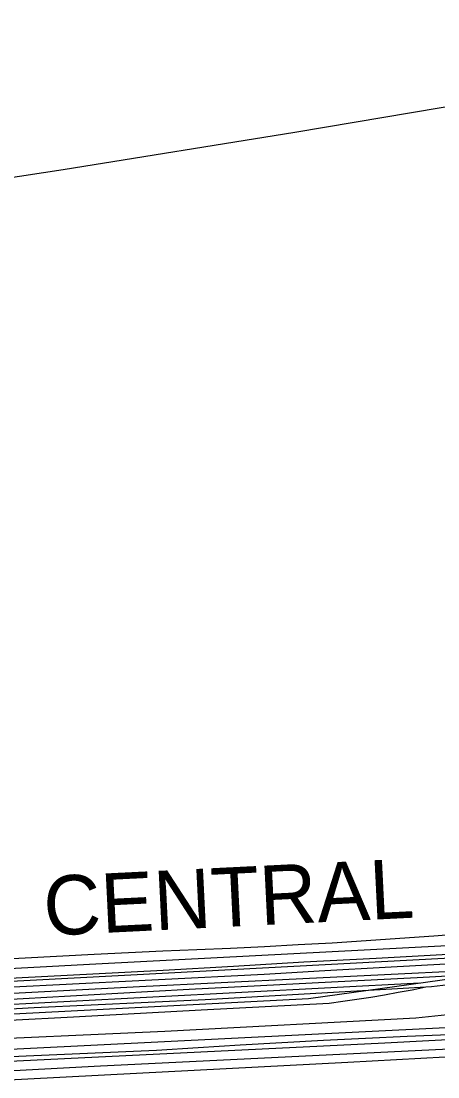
# Model space of a CAD drawing. Extents: x 3508733 to 3546731, y 546897 to 572481.
# Drawn here: x 3516762 to 3517344, y 567889 to 569367 of the extents above; entities that cross this region are included whole.
import ezdxf

# ---------------------------------------------------------------- set-up
doc = ezdxf.new("R2010")
doc.units = 0
for name, color, linetype in [('V-DTCH-CNTR', 7, 'Continuous'), ('V-RAIL-IDEN', 7, 'Continuous'), ('V-RAIL-TRAK', 7, 'Continuous'), ('V-ROAD-CNTR', 7, 'Continuous'), ('V-TOPO-SHOR', 7, 'Continuous')]:
    doc.layers.add(name, color=color, linetype=linetype)

msp = doc.modelspace()

# ---------------------------------------------------------------- linework, layer by layer
at = {"layer": 'V-DTCH-CNTR'}
for points in [[(3518426.588, 569365.362), (3518194.0670000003, 569343.415), (3517851.477, 569304.839), (3517537.957, 569270.982), (3517390.579, 569252.3200000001), (3517144.465, 569210.947), (3516820.739, 569158.495), (3516438.882, 569100.279), (3516292.9, 569076.452), (3516001.605, 569018.555)], [(3516671.532, 568051.006), (3516767.6720000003, 568056.139), (3516863.821, 568061.068), (3516959.981, 568065.799), (3517007.349, 568067.632), (3517054.7090000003, 568069.697), (3517102.057, 568071.99), (3517149.394, 568074.515), (3517196.717, 568077.27), (3517244.028, 568080.254), (3517291.323, 568083.4670000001), (3517338.603, 568086.912), (3517385.862, 568090.586), (3517433.106, 568094.49), (3517555.615, 568102.198), (3517785.2800000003, 568111.175), (3518030.47, 568123.776), (3518316.304, 568142.4720000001)]]:
    msp.add_lwpolyline(points, dxfattribs=at)
at = {"layer": 'V-RAIL-TRAK'}
for points in [[(3518351.019, 568114.087), (3517994.9420000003, 568095.057), (3517908.188, 568090.0970000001), (3517821.421, 568085.388), (3517734.6410000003, 568080.932), (3517647.847, 568076.725), (3517561.042, 568072.7710000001), (3517460.045, 568066.733), (3517359.038, 568060.904), (3517258.0160000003, 568055.285), (3517156.986, 568049.872), (3517058.6580000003, 568044.06), (3516960.315, 568038.479), (3516861.9590000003, 568033.129), (3516763.594, 568028.012), (3516631.881, 568020.637)], [(3516658.474, 568011.0380000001), (3516806.215, 568018.505), (3516953.958, 568025.925), (3517101.702, 568033.297), (3517186.295, 568038.323), (3517270.9, 568043.1630000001), (3517355.5130000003, 568047.81), (3517440.1380000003, 568052.268), (3517561.822, 568058.0480000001), (3517683.4960000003, 568064.062), (3517805.16, 568070.317), (3517926.809, 568076.809), (3518047.336, 568083.355), (3518167.8710000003, 568089.806), (3518288.41, 568096.165), (3518408.951, 568102.43), (3518489.861, 568106.165), (3518506.895, 568107.005), (3518570.757, 568110.153), (3518651.6410000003, 568114.39)], [(3518944.605, 568113.3740000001), (3518863.767, 568109.284), (3518703.052, 568101.457), (3518542.3310000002, 568093.812), (3518391.555, 568086.017), (3518240.79, 568077.983), (3518124.424, 568071.595), (3518090.039, 568069.709), (3517983.031, 568063.409), (3517876.006, 568057.366), (3517768.969, 568051.578), (3517661.921, 568046.044), (3517554.855, 568040.7660000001), (3517463.369, 568035.943), (3517435.191, 568034.459), (3517315.52, 568028.206), (3517195.849, 568022.013), (3517096.316, 568016.84), (3516996.79, 568011.562), (3516897.269, 568006.182), (3516797.755, 568000.693), (3516698.244, 567995.1)], [(3514632.095, 567871.17), (3515067.864, 567895.049), (3515329.14, 567908.8470000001), (3515365.572, 567910.772), (3515437.473, 567914.7220000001), (3515592.12, 567923.2220000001), (3515724.822, 567929.648), (3515852.7770000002, 567935.845), (3516133.963, 567951.345), (3516467.6520000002, 567968.837), (3516780.021, 567986.652), (3517019.09, 567997.736), (3517288.015, 568013.268), (3517327.523, 568015.382), (3517335.457, 568015.805), (3517351.544, 568017.653), (3517367.609, 568019.691), (3517383.646, 568021.921), (3517399.656, 568024.344), (3517415.636, 568026.959), (3517431.5840000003, 568029.763), (3517447.495, 568032.759), (3517463.369, 568035.943)], [(3515688.775, 567912.302), (3515729.616, 567914.927), (3515753.156, 567916.443), (3515817.549, 567920.387), (3515881.957, 567924.133), (3515946.372, 567927.68), (3516010.8000000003, 567931.031), (3516075.239, 567934.18), (3516220.573, 567941.502), (3516365.899, 567948.9670000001), (3516511.217, 567956.5750000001), (3516656.5270000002, 567964.331), (3516835.161, 567973.627), (3517013.788, 567983.113), (3517192.4020000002, 567992.792), (3517211.809, 567995.352), (3517231.187, 567998.133), (3517250.5330000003, 568001.14), (3517269.839, 568004.367), (3517289.111, 568007.818), (3517308.339, 568011.488), (3517327.523, 568015.382)], [(3517955.024, 567963.93), (3517946.724, 567961.046), (3517938.358, 567958.357), (3517929.93, 567955.863), (3517921.4450000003, 567953.5650000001), (3517912.907, 567951.461), (3517904.324, 567949.559), (3517895.698, 567947.855), (3517887.035, 567946.35), (3517878.339, 567945.047), (3517869.614, 567943.947), (3517860.867, 567943.0480000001), (3517852.102, 567942.354), (3517774.886, 567937.84), (3517697.656, 567933.564), (3517620.414, 567929.523), (3517543.159, 567925.718), (3517465.894, 567922.148), (3517388.619, 567918.814), (3517218.582, 567909.791), (3517048.54, 567900.823), (3516878.495, 567891.916), (3516708.447, 567883.066)], [(3517359.9760000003, 567948.537), (3517301.536, 567946.018), (3517243.105, 567943.276), (3517184.685, 567940.308), (3517126.276, 567937.1190000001), (3517067.882, 567933.705), (3517009.4990000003, 567930.068), (3516951.133, 567926.205), (3516876.1380000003, 567923.176), (3516801.15, 567919.928), (3516726.173, 567916.461)]]:
    msp.add_lwpolyline(points, dxfattribs=at)
at = {"layer": 'V-ROAD-CNTR'}
for points in [[(3521093.579774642, 568241.175491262), (3520798.753364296, 568217.342538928), (3520420.0671216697, 568201.5255705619), (3520267.1584274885, 568189.4725946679), (3519841.37827905, 568172.7476281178), (3519690.082581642, 568163.657646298), (3519221.228519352, 568133.27170707), (3518627.7027064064, 568097.0117795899), (3518514.3509331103, 568086.1288013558), (3518236.049489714, 568067.9378377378), (3518067.9988258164, 568075.11182339), (3517535.933889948, 568046.7418801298), (3517450.66806048, 568038.8758958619), (3517163.540634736, 567998.805976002), (3515683.694594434, 567921.754130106), (3515524.090913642, 567914.3611448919), (3515291.0693796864, 567900.9091717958), (3514216.1605295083, 567847.25227911), (3513979.474002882, 567857.10225941)], [(3518191.93657794, 568122.255729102), (3517571.750818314, 568083.99180563), (3516866.270229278, 568047.0918794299), (3516165.4296309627, 568009.3579548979), (3515708.402545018, 567981.5080105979), (3515316.140329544, 567964.803044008), (3514386.3821890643, 567914.4681446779), (3513892.8151762, 567898.4101767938), (3513315.912330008, 567858.51225659), (3512893.95217393, 567835.829301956)], [(3518542.79587622, 568118.0607374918), (3518357.489246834, 568109.178755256), (3517909.0841436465, 568085.4698026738), (3517484.710992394, 568062.228849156), (3516968.1700254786, 568034.56190449), (3515719.4745228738, 567968.4760366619), (3514984.8079922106, 567932.899107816), (3513660.4756408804, 567861.905249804), (3512913.6481345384, 567818.681336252)], [(3517498.096965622, 568043.2508871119), (3516927.445106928, 568015.382942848), (3515733.3034952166, 567952.6120683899), (3515145.000671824, 567920.3921328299), (3513966.9600279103, 567863.441246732), (3513481.253999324, 567836.200301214), (3512928.204105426, 567802.83736794)], [(3517319.3583231, 568020.5509325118), (3516697.0175677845, 567988.162997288), (3515719.543522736, 567941.51709058), (3515389.0901836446, 567922.1601292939)], [(3515997.449966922, 567890.9581916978), (3518114.049733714, 567996.3189809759)], [(3518017.1819274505, 567976.413020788), (3517270.545420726, 567936.87709986), (3516031.413898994, 567875.93222175)], [(3516145.867670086, 567865.9592416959), (3516872.90421601, 567904.9541637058), (3517857.380247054, 567953.021067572)]]:
    msp.add_lwpolyline(points, dxfattribs=at)
msp.add_spline([(3518521.097919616, 568161.867649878), (3518476.2020094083, 568160.5396525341), (3518343.213275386, 568156.6056604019), (3518234.7574922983, 568152.6686682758), (3518103.5127547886, 568139.0706954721), (3517970.860020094, 568131.9897096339), (3517852.533256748, 568125.0887234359), (3517723.7565143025, 568118.3647368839), (3517607.51274679, 568114.925743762), (3517582.380797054, 568118.797736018), (3517561.9568379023, 568135.9237017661), (3517552.0888576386, 568157.492658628), (3517542.5248767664, 568216.7205401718), (3517513.4509349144, 568461.907049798), (3517473.805014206, 568734.7165041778), (3517430.5471007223, 569006.446960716), (3517389.360183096, 569273.867425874), (3517369.6082226, 569416.103141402), (3517334.4922928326, 569658.9276557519), (3517298.566364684, 569879.8682138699), (3517262.397437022, 570109.059755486), (3517248.069465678, 570207.4935586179), (3517236.221489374, 570287.7823980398), (3517232.3614970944, 570360.7792520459), (3517217.689526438, 570470.8610318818), (3517214.6575325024, 570512.2239491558)], degree=3, dxfattribs=at)
at = {"layer": 'V-TOPO-SHOR'}
msp.add_lwpolyline([(3515876.8140000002, 567898.953), (3516077.8680000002, 567908.466), (3516337.725, 567923.301), (3516651.495, 567939.515), (3516962.821, 567953.2980000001), (3517313.455, 567972.156), (3517534.955, 567995.622), (3517547.14, 567996.2000000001), (3517548.6720000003, 567999.546), (3517549.907, 568006.243), (3517549.629, 568015.687), (3517549.659, 568027.262)], dxfattribs=at)

# ---------------------------------------------------------------- texts
at = {"layer": 'V-RAIL-IDEN'}
msp.add_text('CENTRAL', height=82.99983200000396, rotation=2.8207551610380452, dxfattribs=at).set_placement((3516795.1759428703, 568086.83449408))

doc.saveas('drawing.dxf')
